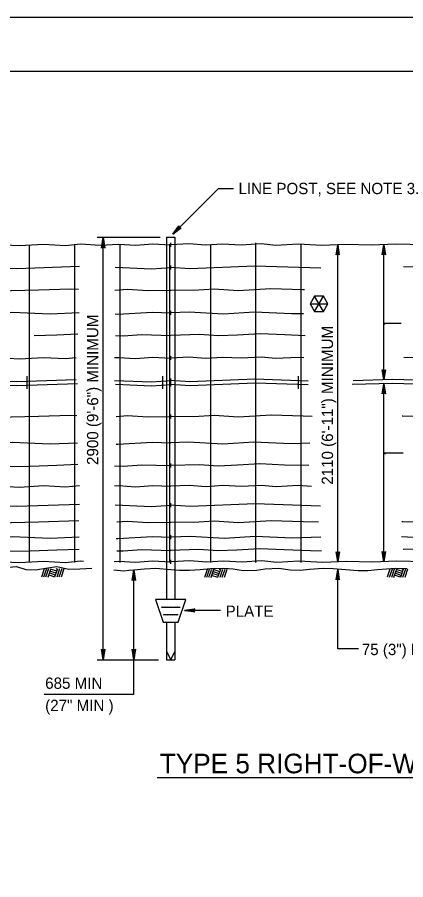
# Model space of a CAD drawing. Extents: x 13 to 918, y -903 to 879.
# Drawn here: x 210.4 to 317.7, y 640.9 to 878.9 of the extents above; entities that cross this region are included whole.
import ezdxf

# ---------------------------------------------------------------- set-up
doc = ezdxf.new("R2010")
doc.units = 0
for name, color, linetype in [('1', 7, 'Continuous'), ('2', 7, 'Continuous'), ('3', 7, 'Continuous'), ('PLT-BNDY', 7, 'Continuous')]:
    doc.layers.add(name, color=color, linetype=linetype)

msp = doc.modelspace()

# ---------------------------------------------------------------- linework, layer by layer
at = {"layer": '1'}
for p, q in [((217.82925, 726.662), (217.05625, 724.435)), ((218.425, 726.662), (217.6375, 724.39325)), ((219.021, 726.662), (218.2335, 724.39325)), ((219.61675, 726.662), (218.82925, 724.39325)), ((221.1105, 725.489), (219.41475, 726.07875)), ((221.29375, 726.02025), (219.598, 726.60775)), ((221.498, 726.662), (220.7125, 724.39325)), ((221.47725, 726.5515), (221.1625, 726.662)), ((222.09375, 726.662), (221.3085, 724.39325)), ((222.6875, 726.662), (221.90425, 724.39325)), ((223.2855, 726.662), (222.5, 724.39325)), ((262.82925, 726.5265), (262.05625, 724.2995)), ((263.425, 726.5265), (262.6375, 724.25775)), ((264.021, 726.5265), (263.2335, 724.25775)), ((264.61675, 726.5265), (263.82925, 724.25775)), ((266.29375, 725.885), (264.598, 726.4725)), ((266.498, 726.5265), (265.7125, 724.25775)), ((266.47725, 726.41625), (266.1625, 726.5265)), ((267.09375, 726.5265), (266.3085, 724.25775)), ((267.6875, 726.5265), (266.90425, 724.25775)), ((268.2855, 726.5265), (267.5, 724.25775)), ((313.31475, 726.58275), (312.54175, 724.35575)), ((313.9105, 726.58275), (313.123, 724.314)), ((314.50625, 726.58275), (313.71875, 724.314)), ((315.10225, 726.58275), (314.31475, 724.314)), ((316.77925, 725.94125), (315.0835, 726.52875)), ((316.9835, 726.58275), (316.198, 724.314)), ((316.9625, 726.4725), (316.648, 726.58275)), ((317.57925, 726.58275), (316.79375, 724.314)), ((318.173, 726.58275), (317.38975, 724.314)), ((219.1085, 724.39325), (218.8605, 724.48075)), ((220.74175, 724.4265), (219.04375, 725.012)), ((220.92725, 724.95775), (219.22925, 725.54325)), ((264.1085, 724.25775), (263.8605, 724.34525)), ((265.74175, 724.29125), (264.04375, 724.8765)), ((265.92725, 724.8225), (264.22925, 725.40775)), ((266.1105, 725.35375), (264.41475, 725.94325)), ((314.59375, 724.314), (314.346, 724.4015)), ((316.22725, 724.3475), (314.52925, 724.93275)), ((316.4125, 724.87875), (314.71475, 725.464)), ((316.596, 725.41), (314.9, 725.9995))]:
    msp.add_line(p, q, dxfattribs=at)
msp.add_lwpolyline([(839.2505, 299.93025), (839.2505, 863.93025), (53.2505, 863.93025), (53.2505, 299.93025), (839.2505, 299.93025), (839.2505, 326.28925), (639.2505, 326.28925), (639.2505, 390.96675), (839.2505, 390.96675), (839.2505, 419.93025), (639.2505, 419.93025), (639.2505, 299.93025), (718.052, 299.93025), (718.052, 326.28925), (718.052, 299.93025), (795.052, 299.93025), (795.052, 326.28925), (795.052, 313.97275), (839.2505, 313.97275)], dxfattribs=at)
at = {"layer": '2'}
for p, q in [((232.496, 818.2225), (249.89375, 818.2225)), ((234.1085, 701.54525), (234.1085, 818.2225)), ((251.598, 818.2225), (253.948, 818.2225)), ((251.598, 818.2225), (251.598, 718.185)), ((253.948, 818.2225), (253.948, 718.2265)), ((276.2105, 816.64125), (276.2105, 728.47025)), ((213.7105, 816.1225), (213.7105, 728.47025)), ((226.2105, 816.29525), (226.2105, 738.15375)), ((238.7105, 816.29525), (238.7105, 728.47025)), ((252.41875, 816.29525), (252.41875, 728.47025)), ((252.773, 816.12875), (252.773, 816.12875)), ((263.7105, 816.14125), (263.7105, 728.47025)), ((288.7105, 816.3515), (288.7105, 728.47025)), ((298.8855, 728.61), (298.8855, 816.1225)), ((311.623, 778.84525), (311.623, 816.1725)), ((252.773, 809.889), (252.773, 809.889)), ((252.773, 797.37875), (252.773, 797.37875)), ((316.396, 794.44325), (311.623, 794.44325)), ((252.773, 784.87875), (252.773, 784.87875)), ((212.99375, 779.87025), (212.99375, 776.34125)), ((250.49375, 779.87025), (250.49375, 776.34125)), ((252.773, 778.639), (252.773, 778.639)), ((287.99375, 779.87025), (287.99375, 776.34125)), ((252.773, 777.587), (252.773, 777.587)), ((311.623, 728.662), (311.623, 777.79125)), ((252.773, 768.73275), (252.773, 768.73275)), ((252.773, 761.44125), (252.773, 761.44125)), ((317.00225, 758.59325), (311.623, 758.59325)), ((252.773, 755.19125), (252.773, 755.19125)), ((252.773, 749.462), (252.773, 749.462)), ((252.773, 744.25375), (252.773, 744.25375)), ((226.2105, 738.15375), (226.2105, 728.47025)), ((252.773, 739.56625), (252.773, 739.56625)), ((252.773, 735.3995), (252.773, 735.3995)), ((252.773, 731.75375), (252.773, 731.75375)), ((252.773, 728.62875), (252.773, 728.62875)), ((242.5875, 692.1325), (242.5875, 726.437)), ((252.773, 726.54525), (252.773, 726.54525)), ((252.773, 726.54525), (252.773, 726.54525)), ((252.773, 726.54525), (252.773, 726.54525)), ((298.8855, 704.61725), (298.8855, 726.46625)), ((256.93975, 718.2225), (248.60625, 718.2225)), ((248.60625, 718.2225), (250.68975, 711.9725)), ((254.85625, 711.9725), (256.93975, 718.2225)), ((250.19175, 716.139), (255.3875, 716.139)), ((266.51475, 715.20375), (256.60625, 715.20375)), ((250.68975, 714.05575), (254.85625, 714.05575)), ((250.68975, 711.9725), (254.85625, 711.9725)), ((251.598, 711.987), (251.598, 701.54525)), ((253.948, 711.96625), (253.948, 701.54525)), ((251.598, 703.90575), (252.773, 701.55575)), ((252.773, 701.55575), (253.948, 703.90575)), ((304.621, 704.61725), (298.8855, 704.61725)), ((232.45625, 701.54525), (249.39375, 701.54525)), ((251.598, 701.54525), (253.948, 701.54525)), ((217.85675, 692.1325), (242.5875, 692.1325))]:
    msp.add_line(p, q, dxfattribs=at)
for points in [[(252.773, 815.58075), (252.75625, 815.7725), (252.7875, 815.88275), (252.7605, 816.03075), (252.79375, 816.1725), (252.75625, 816.33075), (252.7835, 816.489), (252.773, 816.6765)], [(204.45225, 816.237), (211.03125, 815.89325), (217.6105, 816.314), (223.72925, 815.97025), (227.81475, 816.39125), (233.3, 816.04525), (238.44175, 816.314), (243.046, 815.989), (247.7835, 816.39125), (252.773, 816.12875)], [(322.65425, 816.10375), (315.021, 816.314), (308.173, 816.0265), (301.09375, 816.237), (294.51475, 815.89325), (287.9355, 816.314), (281.81675, 815.97025), (277.73125, 816.39125), (272.246, 816.04525), (267.10425, 816.314), (262.5, 815.989), (257.7625, 816.39125), (252.773, 816.12875)], [(101.2105, 809.889), (102.773, 809.889), (108.38975, 809.9765), (113.77925, 810.0725), (119.171, 809.612), (130.2375, 810.0725), (145.56475, 809.70775), (162.675, 810.0725), (173.16675, 809.612), (191.46675, 810.16825), (210.24375, 809.612), (227.598, 810.1975)], [(237.396, 809.937), (247.496, 809.51625), (252.773, 809.889)], [(252.773, 809.34125), (252.75625, 809.53275), (252.7875, 809.64325), (252.7605, 809.79125), (252.79375, 809.93275), (252.75625, 810.09125), (252.7835, 810.2495), (252.773, 810.437)], [(294.221, 809.6495), (275.9855, 810.264), (258.05, 809.51625), (252.773, 809.889)], [(402.7, 809.92025), (402.773, 809.889), (397.15625, 809.9765), (391.76675, 810.0725), (386.375, 809.612), (375.3085, 810.0725), (359.98125, 809.70775), (342.871, 810.0725), (332.37925, 809.612), (317.0125, 810.07875)], [(101.2105, 803.639), (102.773, 803.639), (108.63975, 803.639), (114.6625, 803.81), (120.148, 803.3495), (127.13125, 803.735), (133.173, 803.44525), (139.196, 803.735), (145.9855, 803.3495), (155.00225, 803.90575), (161.13975, 803.44525), (168.5625, 803.81), (174.796, 803.54125), (182.96875, 803.54125), (188.74175, 803.735), (195.33975, 804.0015), (202.898, 803.4265), (208.748, 803.5225), (216.2875, 803.69525), (225.1105, 803.98275), (227.30225, 803.8475)], [(237.375, 803.6495), (240.821, 803.887), (246.47925, 803.5225), (252.773, 803.639)], [(289.7235, 803.72125), (289.2585, 803.69525), (280.4355, 803.98275), (271.421, 803.4265), (264.725, 803.887), (259.06675, 803.5225), (252.773, 803.639)], [(101.2105, 797.389), (102.773, 797.389), (107.56475, 797.085), (112.49375, 797.46825), (118.25, 797.564), (123.448, 797.2765), (129.5855, 797.564), (135.91475, 797.18075), (142.975, 797.564), (150.225, 797.18075), (158.03125, 797.564), (166.1085, 797.18075), (174.6625, 797.564), (184.42725, 797.18075), (192.3105, 797.64125), (199.90625, 797.10375), (209.01675, 797.564), (219.4335, 797.10375), (227.4585, 797.464)], [(237.4085, 797.05775), (238.19175, 797.00775), (247.66875, 797.564), (252.773, 797.37875)], [(252.773, 796.83075), (252.75625, 797.0225), (252.7875, 797.13275), (252.7605, 797.28075), (252.79375, 797.4225), (252.75625, 797.58075), (252.7835, 797.739), (252.773, 797.9265)], [(289.4355, 797.09375), (286.1125, 797.10375), (275.88975, 797.564), (267.35425, 797.00775), (257.87725, 797.564), (252.773, 797.37875)], [(215.047, 791.05025), (221.29375, 791.27875), (227.15, 791.5265)], [(237.5355, 791.085), (239.59175, 791.01), (244.8105, 791.3745), (252.773, 791.12875)], [(289.91575, 791.04275), (284.25225, 791.27875), (277.4625, 791.56625), (271.248, 791.2015), (265.95425, 791.01), (260.7355, 791.3745), (252.773, 791.12875)], [(101.2105, 784.889), (102.773, 784.889), (104.91875, 784.79525), (109.11875, 785.064), (113.223, 784.72025), (119.18975, 785.064), (125.5, 784.72025), (131.75425, 785.064), (136.89375, 784.72025), (142.59175, 785.064), (146.85, 784.72025), (152.68125, 785.064), (158.4355, 784.72025), (165.09175, 785.00775), (170.03975, 784.79525), (176.79175, 785.064), (182.89175, 784.85375), (190.525, 785.064), (197.373, 784.7765), (204.45225, 784.987), (211.03125, 784.64325), (217.6105, 785.064), (223.72925, 784.72025), (226.675, 785.0245)], [(237.21475, 784.9995), (238.44175, 785.064), (243.046, 784.739), (247.7835, 785.14125), (252.773, 784.87875)], [(252.773, 784.33075), (252.75625, 784.5225), (252.7875, 784.63275), (252.7605, 784.78075), (252.79375, 784.9225), (252.75625, 785.08075), (252.7835, 785.239), (252.773, 785.4265)], [(289.54175, 784.96), (287.9355, 785.064), (281.81675, 784.72025), (277.73125, 785.14125), (272.246, 784.79525), (267.10425, 785.064), (262.5, 784.739), (257.7625, 785.14125), (252.773, 784.87875)], [(402.548, 784.87875), (402.773, 784.889), (400.62725, 784.79525), (396.42725, 785.064), (392.323, 784.72025), (386.35625, 785.064), (380.046, 784.72025), (373.79175, 785.064), (368.65225, 784.72025), (362.95425, 785.064), (358.696, 784.72025), (352.86475, 785.064), (347.1105, 784.72025), (340.45425, 785.00775), (335.50625, 784.79525), (328.75425, 785.064), (322.65425, 784.85375), (317.17925, 785.00375)], [(188.375, 778.8245), (191.46675, 778.91825), (210.24375, 778.362), (226.6855, 778.91625)], [(237.23975, 778.69325), (247.496, 778.26625), (252.773, 778.639)], [(252.773, 778.09125), (252.75625, 778.28275), (252.7875, 778.39325), (252.7605, 778.54125), (252.79375, 778.68275), (252.75625, 778.84125), (252.7835, 778.9995), (252.773, 779.187)], [(290.7585, 778.51625), (275.9855, 779.014), (258.05, 778.26625), (252.773, 778.639)], [(402.773, 778.639), (402.773, 778.639), (397.15625, 778.7265), (391.76675, 778.8225), (386.375, 778.362), (375.3085, 778.8225), (359.98125, 778.45775), (342.871, 778.8225), (332.37925, 778.362), (314.07925, 778.91825), (303.173, 778.59525)], [(188.44175, 777.7745), (191.46675, 777.86625), (210.24375, 777.31), (226.996, 777.8745)], [(237.546, 777.62875), (247.496, 777.214), (252.773, 777.587)], [(252.773, 777.039), (252.75625, 777.23075), (252.7875, 777.34125), (252.7605, 777.489), (252.79375, 777.63075), (252.75625, 777.789), (252.7835, 777.9475), (252.773, 778.135)], [(290.7605, 777.46625), (276.05625, 777.962), (258.121, 777.214), (252.84375, 777.587)], [(402.773, 777.587), (402.84375, 777.587), (397.22725, 777.6745), (391.8375, 777.77025), (386.446, 777.31), (375.37925, 777.77025), (360.05225, 777.40575), (342.94175, 777.77025), (332.45, 777.31), (314.15, 777.86625), (302.86675, 777.53275)], [(133.925, 768.5745), (139.196, 768.82875), (145.9855, 768.44325), (155.00225, 768.9995), (161.13975, 768.539), (168.5625, 768.90375), (174.796, 768.635), (182.96875, 768.635), (188.74175, 768.82875), (195.33975, 769.09525), (202.898, 768.52025), (208.748, 768.61625), (216.2875, 768.789), (225.1105, 769.0765), (226.823, 768.97025)], [(237.69175, 768.76625), (240.821, 768.98075), (246.47925, 768.61625), (252.773, 768.73275)], [(252.773, 768.185), (252.75625, 768.3765), (252.7875, 768.487), (252.7605, 768.635), (252.79375, 768.7765), (252.75625, 768.935), (252.7835, 769.09325), (252.773, 769.28075)], [(291.80575, 768.73375), (289.32925, 768.789), (280.50625, 769.0765), (271.49175, 768.52025), (264.796, 768.98075), (259.1375, 768.61625), (252.84375, 768.73275)], [(402.773, 768.73275), (402.773, 768.73275), (396.97725, 768.73275), (390.95425, 768.90375), (385.46875, 768.44325), (378.4855, 768.82875), (372.44375, 768.539), (366.421, 768.82875), (359.63125, 768.44325), (350.61475, 768.9995), (344.47725, 768.539), (337.05425, 768.90375), (330.821, 768.635), (322.648, 768.635), (316.875, 768.82875), (316.71675, 768.835)], [(126.11675, 761.464), (129.5855, 761.6265), (135.91475, 761.24325), (142.975, 761.6265), (150.225, 761.24325), (158.03125, 761.6265), (166.1085, 761.24325), (174.6625, 761.6265), (184.42725, 761.24325), (192.3105, 761.70375), (199.90625, 761.16625), (209.01675, 761.6265), (219.4335, 761.16625), (226.99175, 761.50575)], [(237.70425, 761.1015), (238.19175, 761.07025), (247.66875, 761.6265), (252.773, 761.44125)], [(291.223, 761.4015), (285.91675, 761.16625), (275.69375, 761.6265), (267.1585, 761.07025), (257.68125, 761.6265), (252.57725, 761.44125)], [(122.31675, 755.40375), (127.87925, 755.09125), (133.825, 755.37875), (139.598, 755.37875), (145.448, 754.8995), (151.7605, 755.187), (157.99375, 755.45575), (163.84375, 754.8995), (170.90225, 754.99525), (179.55425, 755.5515), (188.28125, 755.45575), (196.473, 754.99525), (202.34175, 755.264), (207.73125, 754.9765), (213.946, 755.0725), (221.29375, 755.34125), (227.146, 755.5915)], [(237.22925, 755.15775), (239.59175, 755.0725), (244.8105, 755.437), (252.773, 755.19125)], [(290.876, 755.2165), (284.2105, 755.34125), (277.421, 755.62875), (271.20625, 755.264), (265.9125, 755.0725), (260.69375, 755.437), (252.73125, 755.19125)], [(252.773, 754.64325), (252.75625, 754.835), (252.7875, 754.94525), (252.7605, 755.09325), (252.79375, 755.235), (252.75625, 755.39325), (252.7835, 755.5515), (252.773, 755.739)], [(111.51875, 749.4475), (113.223, 749.30375), (119.18975, 749.6475), (125.5, 749.30375), (131.75425, 749.6475), (136.89375, 749.30375), (142.59175, 749.6475), (146.85, 749.30375), (152.68125, 749.6475), (158.4355, 749.30375), (165.09175, 749.59125), (170.03975, 749.37875), (176.79175, 749.6475), (182.89175, 749.437), (190.525, 749.6475), (197.373, 749.36), (204.45225, 749.57025), (211.03125, 749.2265), (217.6105, 749.6475), (223.72925, 749.30375), (227.54675, 749.702)], [(237.2125, 749.58275), (238.44175, 749.6475), (243.046, 749.3225), (247.7835, 749.7245), (252.773, 749.462)], [(291.6445, 749.4535), (288.00625, 749.6475), (281.8875, 749.30375), (277.80225, 749.7245), (272.31675, 749.37875), (267.175, 749.6475), (262.571, 749.3225), (257.8335, 749.7245), (252.84375, 749.462)], [(101.2105, 744.264), (102.773, 744.264), (108.38975, 744.3515), (113.77925, 744.4475), (119.171, 743.987), (130.2375, 744.4475), (145.56475, 744.08275), (162.675, 744.4475), (173.16675, 743.987), (191.46675, 744.54325), (210.24375, 743.987), (227.55625, 744.571)], [(237.3835, 744.312), (247.496, 743.89125), (252.773, 744.264)], [(252.773, 743.70575), (252.75625, 743.8975), (252.7875, 744.00775), (252.7605, 744.15575), (252.79375, 744.2975), (252.75625, 744.45575), (252.7835, 744.614), (252.773, 744.8015)], [(294.17725, 744.02825), (276.05625, 744.639), (258.121, 743.89125), (252.84375, 744.264)], [(101.2105, 739.5765), (102.773, 739.5765), (108.63975, 739.5765), (114.6625, 739.7475), (120.148, 739.287), (127.13125, 739.6725), (133.173, 739.38275), (139.196, 739.6725), (145.9855, 739.287), (155.00225, 739.84325), (161.13975, 739.38275), (168.5625, 739.7475), (174.796, 739.47875), (182.96875, 739.47875), (188.74175, 739.6725), (195.33975, 739.939), (202.898, 739.364), (208.748, 739.46), (216.2875, 739.63275), (227.39825, 739.996)], [(237.8625, 739.62025), (240.821, 739.8245), (246.47925, 739.46), (252.773, 739.5765)], [(293.58975, 739.535), (289.32925, 739.63275), (280.50625, 739.92025), (271.49175, 739.364), (264.796, 739.8245), (259.1375, 739.46), (252.84375, 739.5765)], [(373.69175, 739.44325), (350.61475, 739.84325), (344.47725, 739.38275), (337.05425, 739.7475), (330.821, 739.47875), (322.648, 739.47875), (316.875, 739.6725), (316.548, 739.685)], [(101.2105, 735.41), (102.773, 735.41), (107.56475, 735.10575), (112.49375, 735.489), (118.25, 735.585), (123.448, 735.2975), (129.5855, 735.585), (135.91475, 735.2015), (142.975, 735.585), (150.225, 735.2015), (158.03125, 735.585), (166.1085, 735.2015), (174.6625, 735.585), (184.42725, 735.2015), (192.3105, 735.662), (199.90625, 735.1245), (209.01675, 735.585), (219.4335, 735.1245), (227.446, 735.485)], [(237.68125, 735.062), (238.19175, 735.02875), (247.66875, 735.585), (252.773, 735.3995)], [(252.773, 734.8515), (252.75625, 735.04325), (252.7875, 735.15375), (252.7605, 735.3015), (252.79375, 735.44325), (252.75625, 735.6015), (252.7835, 735.76), (252.773, 735.9475)], [(294.223, 735.4725), (286.3375, 735.1245), (276.11475, 735.585), (267.57925, 735.02875), (258.10225, 735.585), (252.998, 735.3995)], [(402.773, 735.3995), (402.998, 735.41), (398.20625, 735.10575), (393.27725, 735.489), (387.521, 735.585), (382.323, 735.2975), (376.1855, 735.585), (369.85625, 735.2015), (362.796, 735.585), (355.546, 735.2015), (347.73975, 735.585), (339.6625, 735.2015), (331.1085, 735.585), (321.34375, 735.2015), (316.53125, 735.48275)], [(101.2105, 731.764), (102.773, 731.764), (107.71875, 731.94125), (114.125, 731.65375), (121.375, 732.01825), (127.87925, 731.65375), (133.825, 731.94125), (139.598, 731.94125), (145.448, 731.462), (151.7605, 731.7495), (157.99375, 732.01825), (163.84375, 731.462), (170.90225, 731.55775), (179.55425, 732.114), (188.28125, 732.01825), (196.473, 731.55775), (202.34175, 731.8265), (207.73125, 731.539), (213.946, 731.635), (221.29375, 731.90375), (227.45225, 732.164)], [(237.84175, 731.6975), (239.59175, 731.635), (244.8105, 731.9995), (252.773, 731.75375)], [(294.371, 731.589), (291.40425, 731.635), (284.05625, 731.90375), (277.26675, 732.19125), (271.05225, 731.8265), (265.7585, 731.635), (260.53975, 731.9995), (252.57725, 731.75375)], [(402.773, 731.75375), (402.57725, 731.764), (397.63125, 731.94125), (391.225, 731.65375), (383.975, 732.01825), (377.471, 731.65375), (371.525, 731.94125), (365.75225, 731.94125), (359.90225, 731.462), (353.58975, 731.7495), (347.35625, 732.01825), (341.50625, 731.462), (334.448, 731.55775), (325.796, 732.114), (317.06875, 732.01825), (316.99375, 732.014)], [(204.45225, 728.737), (211.03125, 728.39325), (217.6105, 728.814), (223.72925, 728.47025), (227.81475, 728.89125), (228.68125, 728.837)], [(237.171, 728.7475), (238.44175, 728.814), (243.046, 728.489), (247.7835, 728.89125), (252.773, 728.62875)], [(252.773, 728.08075), (252.75625, 728.2725), (252.7875, 728.38275), (252.7605, 728.53075), (252.79375, 728.6725), (252.75625, 728.83075), (252.7835, 728.989), (252.773, 729.1765)], [(322.87925, 728.60375), (315.246, 728.814), (308.398, 728.5265), (301.31875, 728.737), (294.73975, 728.39325), (288.1605, 728.814), (282.04175, 728.47025), (277.95625, 728.89125), (272.471, 728.54525), (267.32925, 728.814), (262.725, 728.489), (257.9875, 728.89125), (252.998, 728.62875)], [(177.6585, 726.55375), (181.5625, 726.55575), (187.09175, 726.17875), (191.273, 726.83075), (195.475, 726.90775), (198.9085, 726.90775), (202.99375, 726.4475), (207.098, 727.0995), (210.16875, 727.29125), (212.7585, 726.54325), (215.4625, 726.4475), (218.8, 727.00375), (221.3125, 727.29125), (224.6, 726.55775)], [(224.6, 726.55775), (227.6625, 726.685), (230.9605, 726.8765), (230.9835, 726.8765)], [(237.023, 726.3745), (239.84175, 726.11), (241.1855, 726.36), (242.5875, 726.437), (245.5, 726.6475), (248.66475, 726.839), (252.773, 726.54525), (255.1875, 726.3015), (257.95, 726.34125), (260.86475, 726.49325), (263.78125, 726.78075), (267.46475, 726.839), (269.97725, 726.685), (272.7585, 726.24525), (276.47925, 726.34125), (278.8585, 726.7245), (282.598, 726.839), (285.74375, 726.437), (288.54375, 726.28275), (291.05625, 726.57025), (294.8355, 726.8975), (297.65625, 726.762), (301.05, 726.512), (304.54175, 726.2245), (307.16875, 726.2245), (309.875, 726.512), (314.88125, 726.85775), (318.06475, 726.8015)], [(250.19175, 716.139), (250.49175, 716.17875), (250.9335, 716.0995), (251.25425, 716.16), (251.61475, 716.0995), (251.9355, 716.16), (252.298, 716.07875), (252.61875, 716.16), (252.9605, 716.0995), (253.2605, 716.139), (253.6625, 716.0995), (254.023, 716.16), (254.425, 716.11825), (254.746, 716.17875), (255.06675, 716.11825), (255.3875, 716.139)], [(250.68975, 714.05575), (250.973, 714.13275), (251.3335, 714.03275), (251.61475, 714.09325), (251.91675, 714.012), (252.21675, 714.0725), (252.57925, 714.012), (252.83975, 714.09325), (253.17925, 714.012), (253.50225, 714.09325), (253.8625, 714.012), (254.20425, 714.0725), (254.4835, 714.03275), (254.85625, 714.05575)]]:
    msp.add_lwpolyline(points, dxfattribs=at)
at = {"layer": '3'}
for p, q in [((253.398, 819.0975), (265.9355, 831.635)), ((265.9355, 831.635), (270.10225, 831.635)), ((291.2885, 799.87625), (296.17375, 799.87625)), ((292.50925, 797.76175), (294.953, 801.993)), ((294.953, 797.76175), (292.50925, 801.993)), ((249.04053, 669.08875), (383.21194, 669.08875))]:
    msp.add_line(p, q, dxfattribs=at)
for points in [[(255.50625, 820.735), (255.3, 820.8015), (253.398, 819.0975), (255.50625, 820.735), (255.6835, 820.7495), (253.398, 819.0975), (255.1105, 820.989), (255.04175, 821.189), (253.398, 819.0975), (255.05425, 821.37875), (255.04175, 821.189)], [(233.75225, 815.385), (233.9585, 815.49125), (234.1085, 818.2225), (233.75225, 815.385), (233.62725, 815.239), (234.1085, 818.2225), (234.24375, 815.49325), (234.446, 815.39325), (234.1085, 818.2225), (234.5835, 815.239), (234.446, 815.39325)], [(298.55225, 813.4745), (298.74375, 813.5725), (298.8855, 816.1225), (298.55225, 813.4745), (298.4375, 813.337), (298.8855, 816.1225), (299.0105, 813.5745), (299.20225, 813.48075), (298.8855, 816.1225), (299.32725, 813.337), (299.20225, 813.48075)], [(311.28975, 813.5245), (311.48125, 813.6225), (311.623, 816.1725), (311.28975, 813.5245), (311.175, 813.387), (311.623, 816.1725), (311.748, 813.6245), (311.93975, 813.53075), (311.623, 816.1725), (312.06475, 813.387), (311.93975, 813.53075)], [(311.95625, 781.49325), (311.76475, 781.39525), (311.623, 778.84525), (311.95625, 781.49325), (312.071, 781.63075), (311.623, 778.84525), (311.498, 781.39325), (311.30625, 781.487), (311.623, 778.84525), (311.18125, 781.63075), (311.30625, 781.487)], [(311.28975, 775.14325), (311.48125, 775.24125), (311.623, 777.79125), (311.28975, 775.14325), (311.175, 775.00575), (311.623, 777.79125), (311.748, 775.24325), (311.93975, 775.1495), (311.623, 777.79125), (312.06475, 775.00575), (311.93975, 775.1495)], [(299.21875, 731.25775), (299.02725, 731.16), (298.8855, 728.61), (299.21875, 731.25775), (299.3335, 731.39525), (298.8855, 728.61), (298.7605, 731.15775), (298.56875, 731.2515), (298.8855, 728.61), (298.44375, 731.39525), (298.56875, 731.2515)], [(311.95625, 731.31), (311.76475, 731.212), (311.623, 728.662), (311.95625, 731.31), (312.071, 731.4475), (311.623, 728.662), (311.498, 731.21), (311.30625, 731.30375), (311.623, 728.662), (311.18125, 731.4475), (311.30625, 731.30375)], [(242.23125, 723.5995), (242.4375, 723.70575), (242.5875, 726.437), (242.23125, 723.5995), (242.10625, 723.45375), (242.5875, 726.437), (242.723, 723.70775), (242.925, 723.60775), (242.5875, 726.437), (243.0625, 723.45375), (242.925, 723.60775)], [(298.55225, 723.81825), (298.74375, 723.91625), (298.8855, 726.46625), (298.55225, 723.81825), (298.4375, 723.68075), (298.8855, 726.46625), (299.0105, 723.91825), (299.20225, 723.8245), (298.8855, 726.46625), (299.32725, 723.68075), (299.20225, 723.8245)], [(259.25425, 714.87025), (259.15625, 715.062), (256.60625, 715.20375), (259.25425, 714.87025), (259.39175, 714.75575), (256.60625, 715.20375), (259.15425, 715.32875), (259.248, 715.52025), (256.60625, 715.20375), (259.39175, 715.64525), (259.248, 715.52025)], [(234.46475, 704.38275), (234.2585, 704.2765), (234.1085, 701.54525), (234.46475, 704.38275), (234.58975, 704.52875), (234.1085, 701.54525), (233.973, 704.2745), (233.771, 704.3745), (234.1085, 701.54525), (233.6335, 704.52875), (233.771, 704.3745)], [(242.94375, 704.38275), (242.7375, 704.2765), (242.5875, 701.54525), (242.94375, 704.38275), (243.06875, 704.52875), (242.5875, 701.54525), (242.45225, 704.2745), (242.25, 704.3745), (242.5875, 701.54525), (242.1125, 704.52875), (242.25, 704.3745)]]:
    msp.add_lwpolyline(points, dxfattribs=at)
msp.add_lwpolyline([(292.50925, 797.76175), (294.953, 797.76175), (296.17375, 799.87625), (294.953, 801.993), (292.50925, 801.993), (291.2885, 799.87625)], close=True, dxfattribs=at)
at = {"layer": 'PLT-BNDY'}
msp.add_lwpolyline([(13.2505, 878.93025), (854.2505, 878.93025), (854.2505, 284.93025), (13.2505, 284.93025)], close=True, dxfattribs=at)

# ---------------------------------------------------------------- texts
at = {"layer": '3'}
for s, height, p in [('LINE POST, SEE NOTE 3.', 3.1249995, (271.49175, 830.10575)), ('.', 3.125, (311.296, 794.1225)), ('.', 3.125, (311.31675, 758.285)), ('PLATE', 3.124999, (267.923, 713.44525)), ('75 (3") MAX', 3.1249995, (305.5395, 702.87325)), ('685 MIN', 3.124999, (218.1025, 693.569)), ('(27" MIN )', 3.124999, (218.1025, 687.422)), ('TYPE 5 RIGHT-OF-WAY FENCE', 5.4020865, (249.753, 670.26175))]:
    msp.add_text(s, height=height, dxfattribs=at).set_placement(p)
for s, p in [('2900 (9\'-6") MINIMUM', (232.76475, 755.35575)), ('2110 (6\'-11") MINIMUM', (297.5955, 749.8955))]:
    msp.add_text(s, height=3.1249995, rotation=90, dxfattribs=at).set_placement(p)

doc.saveas('drawing.dxf')
